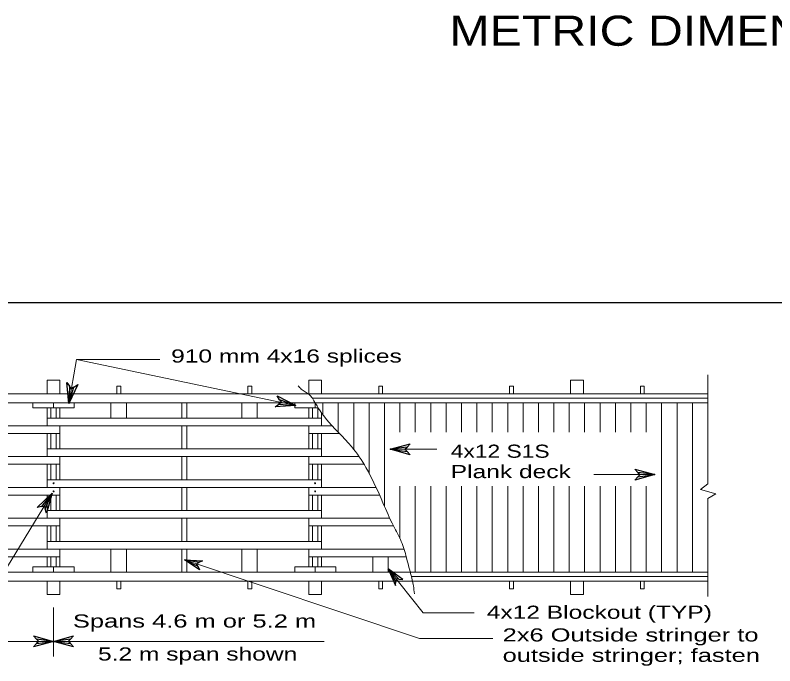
# Model space of a CAD drawing. Extents: x 13426 to 15509, y -9298 to -5111.
# Drawn here: x 15245.4 to 15321.1, y -5416 to -5351.2 of the extents above; entities that cross this region are included whole.
import ezdxf
from ezdxf.enums import TextEntityAlignment as Align

# ---------------------------------------------------------------- set-up
doc = ezdxf.new("R2010")
doc.units = 0
doc.header["$LTSCALE"] = 0.52
for name, color, linetype, lineweight in [('1', 7, 'Continuous', 13), ('11', 7, 'Continuous', 13), ('15', 7, 'Continuous', 13), ('16', 7, 'Continuous', 25), ('2', 7, 'Continuous', 25), ('20', 7, 'Continuous', 13), ('3', 7, 'Continuous', 25), ('30', 7, 'Continuous', 25), ('4', 7, 'Continuous', 13), ('5', 7, 'Continuous', 25), ('6', 7, 'Continuous', 13)]:
    doc.layers.add(name, color=color, linetype=linetype, lineweight=lineweight)
doc.layers.add('19', color=7, linetype='Continuous')

msp = doc.modelspace()

# ---------------------------------------------------------------- linework, layer by layer
at = {"layer": '1'}
for p, q in [((15314.42, -5397.839), (15314.42, -5386.994)), ((15248.583, -5387.513), (15249.861, -5387.513)), ((15248.583, -5388.864), (15248.583, -5387.513)), ((15249.861, -5388.864), (15249.861, -5387.513)), ((15275.94, -5387.513), (15274.662, -5387.513)), ((15274.662, -5388.864), (15274.662, -5387.513)), ((15275.94, -5388.864), (15275.94, -5387.513)), ((15300.741, -5388.864), (15300.741, -5387.513)), ((15302.019, -5387.513), (15300.741, -5387.513)), ((15302.019, -5388.864), (15302.019, -5387.513)), ((15255.55, -5388.119), (15255.933, -5388.119)), ((15255.55, -5388.119), (15255.55, -5388.864)), ((15255.933, -5388.119), (15255.933, -5388.864)), ((15268.59, -5388.119), (15268.973, -5388.119)), ((15268.59, -5388.119), (15268.59, -5388.864)), ((15268.973, -5388.119), (15268.973, -5388.864)), ((15281.629, -5388.119), (15282.012, -5388.119)), ((15281.629, -5388.119), (15281.629, -5388.864)), ((15282.012, -5388.119), (15282.012, -5388.864)), ((15294.669, -5388.119), (15295.052, -5388.119)), ((15294.669, -5388.119), (15294.669, -5388.864)), ((15295.052, -5388.119), (15295.052, -5388.864)), ((15308.091, -5388.119), (15307.708, -5388.119)), ((15307.708, -5388.119), (15307.708, -5388.864)), ((15308.091, -5388.119), (15308.091, -5388.864)), ((15314.42, -5388.864), (15196.297, -5388.864)), ((15314.42, -5389.311), (15275.02, -5389.311)), ((15314.42, -5389.758), (15196.297, -5389.758)), ((15248.583, -5390.273), (15248.583, -5392.06)), ((15249.861, -5390.273), (15249.861, -5391.293)), ((15274.662, -5390.273), (15274.662, -5391.293)), ((15275.94, -5390.778), (15275.94, -5392.06)), ((15249.861, -5392.06), (15249.861, -5394.361)), ((15274.662, -5392.06), (15274.662, -5394.361)), ((15248.583, -5392.827), (15248.583, -5395.128)), ((15275.94, -5392.827), (15275.94, -5395.128)), ((15249.861, -5395.128), (15249.861, -5397.43)), ((15274.662, -5395.128), (15274.662, -5397.43)), ((15248.583, -5395.896), (15248.583, -5398.196)), ((15275.94, -5395.896), (15275.94, -5398.196)), ((15249.861, -5398.196), (15249.861, -5400.497)), ((15274.662, -5398.196), (15274.662, -5400.497)), ((15248.583, -5398.963), (15248.583, -5401.264)), ((15275.94, -5398.963), (15275.94, -5401.264)), ((15314.42, -5409.06), (15314.42, -5399.293)), ((15249.861, -5401.264), (15249.861, -5403.566)), ((15274.662, -5401.264), (15274.662, -5403.566)), ((15248.583, -5402.031), (15248.583, -5404.333)), ((15275.94, -5402.031), (15275.94, -5404.333)), ((15249.861, -5404.333), (15249.861, -5406.12)), ((15274.662, -5404.333), (15274.662, -5406.12)), ((15248.583, -5405.1), (15248.583, -5406.12)), ((15275.94, -5405.1), (15275.94, -5406.12)), ((15314.42, -5406.632), (15196.297, -5406.632)), ((15314.42, -5407.516), (15196.297, -5407.516)), ((15248.583, -5407.518), (15248.583, -5408.869)), ((15249.861, -5408.869), (15249.861, -5407.518)), ((15255.55, -5408.301), (15255.55, -5407.526)), ((15255.933, -5408.301), (15255.933, -5407.526)), ((15268.59, -5408.301), (15268.59, -5407.526)), ((15268.973, -5408.301), (15268.973, -5407.526)), ((15274.662, -5408.869), (15274.662, -5407.518)), ((15275.94, -5407.518), (15275.94, -5408.869)), ((15281.629, -5408.301), (15281.629, -5407.526)), ((15282.012, -5408.301), (15282.012, -5407.526)), ((15314.42, -5407.069), (15284.876, -5407.069)), ((15295.052, -5408.301), (15295.052, -5407.526)), ((15300.741, -5408.869), (15300.741, -5407.518)), ((15302.019, -5407.518), (15302.019, -5408.869)), ((15307.708, -5408.301), (15307.708, -5407.526)), ((15308.091, -5408.301), (15308.091, -5407.526)), ((15255.933, -5408.301), (15255.55, -5408.301)), ((15268.973, -5408.301), (15268.59, -5408.301)), ((15282.012, -5408.301), (15281.629, -5408.301)), ((15308.091, -5408.301), (15307.708, -5408.301)), ((15248.583, -5408.869), (15249.861, -5408.869)), ((15275.94, -5408.869), (15274.662, -5408.869)), ((15302.019, -5408.869), (15300.741, -5408.869))]:
    msp.add_line(p, q, dxfattribs=at)
for points in [[(15314.42, -5397.839), (15313.691, -5398.393), (15315.226, -5398.819), (15314.42, -5399.293)], [(15295.052, -5408.301), (15294.669, -5408.301), (15294.669, -5407.526)]]:
    msp.add_lwpolyline(points, dxfattribs=at)
for points in [[(15275.021, -5389.312), (15274.695, -5388.946), (15273.914, -5388.406), (15273.588, -5388.07)], [(15275.021, -5389.312), (15276.322, -5391.306), (15278.926, -5394.137), (15280.358, -5396.227), (15282.051, -5399.733), (15283.092, -5402.025), (15283.873, -5403.576), (15284.394, -5405.194), (15285.038, -5407.701)]]:
    msp.add_spline(points, degree=3, dxfattribs=at)
at = {"layer": '11'}
for p, q in [((15276.068, -5389.759), (15276.068, -5390.961)), ((15277.602, -5389.759), (15277.602, -5392.713)), ((15279.136, -5389.759), (15279.136, -5394.406)), ((15280.67, -5389.759), (15280.67, -5396.857)), ((15282.204, -5389.759), (15282.204, -5400.07)), ((15283.738, -5389.759), (15283.738, -5392.705)), ((15285.272, -5389.759), (15285.272, -5392.705)), ((15286.806, -5389.759), (15286.806, -5392.705)), ((15288.34, -5389.759), (15288.34, -5392.705)), ((15289.874, -5389.759), (15289.874, -5392.705)), ((15291.408, -5389.759), (15291.408, -5392.705)), ((15292.942, -5389.759), (15292.942, -5392.705)), ((15294.476, -5389.759), (15294.476, -5392.705)), ((15296.01, -5389.759), (15296.01, -5392.705)), ((15297.544, -5389.759), (15297.544, -5392.705)), ((15299.078, -5389.759), (15299.078, -5392.705)), ((15300.612, -5389.759), (15300.612, -5392.705)), ((15302.146, -5389.759), (15302.146, -5392.705)), ((15303.68, -5389.759), (15303.68, -5392.705)), ((15305.214, -5389.759), (15305.214, -5392.705)), ((15306.748, -5389.759), (15306.748, -5392.705)), ((15308.282, -5389.759), (15308.282, -5392.705)), ((15309.817, -5389.758), (15309.817, -5406.632)), ((15311.35, -5389.759), (15311.35, -5392.705)), ((15311.351, -5389.758), (15311.351, -5406.632)), ((15312.885, -5389.758), (15312.885, -5406.632)), ((15283.738, -5398.067), (15283.738, -5403.283)), ((15285.273, -5398.067), (15285.273, -5406.632)), ((15286.807, -5398.067), (15286.807, -5406.632)), ((15288.341, -5398.067), (15288.341, -5406.632)), ((15289.874, -5398.067), (15289.874, -5406.632)), ((15291.408, -5398.067), (15291.408, -5406.632)), ((15292.943, -5398.067), (15292.943, -5406.632)), ((15294.477, -5398.067), (15294.477, -5406.632)), ((15296.011, -5398.067), (15296.011, -5406.632)), ((15297.545, -5398.067), (15297.545, -5406.632)), ((15299.079, -5398.067), (15299.079, -5406.632)), ((15300.613, -5398.067), (15300.613, -5406.632)), ((15302.147, -5398.067), (15302.147, -5406.632)), ((15303.681, -5398.067), (15303.681, -5406.632)), ((15305.215, -5398.067), (15305.215, -5406.632)), ((15306.749, -5398.067), (15306.749, -5406.632)), ((15308.283, -5398.067), (15308.283, -5406.632))]:
    msp.add_line(p, q, dxfattribs=at)
at = {"layer": '15'}
for p, q in [((15251.525, -5385.47), (15250.753, -5389.826)), ((15251.525, -5385.47), (15259.833, -5385.47)), ((15251.525, -5385.47), (15273.362, -5390.03)), ((15287.416, -5394.392), (15282.775, -5394.392)), ((15303.045, -5396.917), (15309.145, -5396.917)), ((15241.981, -5410.423), (15249.092, -5398.762)), ((15262.263, -5405.417), (15285.684, -5413.253)), ((15282.567, -5406.314), (15286.068, -5410.681)), ((15249.222, -5410.145), (15249.222, -5415.034)), ((15291.124, -5410.681), (15286.068, -5410.681)), ((15223.143, -5413.535), (15249.222, -5413.535)), ((15249.222, -5413.536), (15276.177, -5413.536)), ((15285.684, -5413.253), (15292.995, -5413.253))]:
    msp.add_line(p, q, dxfattribs=at)
at = {"layer": '16'}
for points in [[(15251.265, -5388.203), (15251.639, -5387.953), (15250.753, -5389.826), (15250.566, -5387.763), (15250.831, -5388.126), (15250.753, -5389.826), (15251.265, -5388.203), (15251.01, -5388.382), (15250.831, -5388.126)], [(15271.755, -5389.469), (15271.517, -5389.088), (15273.362, -5390.03), (15271.294, -5390.155), (15271.665, -5389.901), (15273.362, -5390.03), (15271.755, -5389.469), (15271.927, -5389.73), (15271.665, -5389.901)], [(15284.462, -5394.613), (15284.774, -5394.937), (15282.775, -5394.392), (15284.774, -5393.847), (15284.462, -5394.171), (15282.775, -5394.392), (15284.462, -5394.613), (15284.242, -5394.392), (15284.462, -5394.171)], [(15307.458, -5396.696), (15307.146, -5396.372), (15309.145, -5396.917), (15307.146, -5397.462), (15307.458, -5397.137), (15309.145, -5396.917), (15307.458, -5396.696), (15307.679, -5396.917), (15307.458, -5397.137)], [(15248.025, -5400.087), (15247.586, -5400.184), (15249.092, -5398.762), (15248.517, -5400.752), (15248.402, -5400.317), (15249.092, -5398.762), (15248.025, -5400.087), (15248.329, -5400.014), (15248.402, -5400.317)], [(15263.598, -5406.05), (15263.768, -5406.401), (15262.263, -5405.417), (15264.059, -5405.501), (15263.716, -5405.686), (15262.263, -5405.417), (15263.598, -5406.05), (15263.474, -5405.809), (15263.716, -5405.686)], [(15283.632, -5407.337), (15284.021, -5407.371), (15282.567, -5406.314), (15283.283, -5407.963), (15283.334, -5407.576), (15282.567, -5406.314), (15283.632, -5407.337), (15283.364, -5407.308), (15283.334, -5407.576)], [(15247.535, -5413.315), (15247.223, -5412.99), (15249.222, -5413.535), (15247.223, -5414.081), (15247.535, -5413.756), (15249.222, -5413.535), (15247.535, -5413.315), (15247.755, -5413.535), (15247.535, -5413.756)], [(15250.91, -5413.756), (15251.221, -5414.081), (15249.222, -5413.536), (15251.221, -5412.99), (15250.91, -5413.315), (15249.222, -5413.536), (15250.91, -5413.756), (15250.689, -5413.536), (15250.91, -5413.315)]]:
    msp.add_lwpolyline(points, dxfattribs=at)
at = {"layer": '2', "lineweight": 13}
for p, q in [((15275.94, -5391.293), (15248.583, -5391.293)), ((15276.968, -5392.06), (15222.376, -5392.06)), ((15249.861, -5392.827), (15222.504, -5392.827)), ((15246.807, -5392.827), (15249.861, -5392.827)), ((15277.716, -5392.827), (15274.662, -5392.827)), ((15275.94, -5394.361), (15248.583, -5394.361)), ((15279.679, -5395.128), (15222.376, -5395.128)), ((15249.861, -5395.896), (15222.504, -5395.896)), ((15280.178, -5395.896), (15274.662, -5395.896)), ((15275.94, -5397.43), (15248.583, -5397.43)), ((15281.329, -5398.196), (15222.376, -5398.196)), ((15249.861, -5398.963), (15222.504, -5398.963)), ((15281.691, -5398.963), (15274.662, -5398.963)), ((15275.94, -5400.497), (15248.583, -5400.497)), ((15282.747, -5401.264), (15222.376, -5401.264)), ((15249.861, -5402.031), (15222.504, -5402.031)), ((15283.096, -5402.031), (15274.662, -5402.031)), ((15275.94, -5403.566), (15248.583, -5403.566)), ((15284.148, -5404.333), (15222.376, -5404.333)), ((15249.861, -5405.1), (15222.504, -5405.1)), ((15284.369, -5405.1), (15274.662, -5405.1))]:
    msp.add_line(p, q, dxfattribs=at)
msp.add_spline([(15285.038, -5407.701), (15285.087, -5407.999), (15285.176, -5408.79)], degree=3, dxfattribs=at)
at = {"layer": '3', "lineweight": 13}
for p, q in [((15247.177, -5390.273), (15247.177, -5389.761)), ((15249.222, -5390.273), (15249.222, -5389.791)), ((15275.301, -5390.273), (15275.301, -5389.791)), ((15247.177, -5390.273), (15249.222, -5390.273)), ((15249.222, -5406.12), (15247.177, -5406.12)), ((15247.177, -5406.12), (15247.177, -5406.632)), ((15251.267, -5406.12), (15249.222, -5406.12)), ((15249.222, -5406.12), (15249.222, -5406.632)), ((15251.267, -5406.12), (15251.267, -5406.632)), ((15273.255, -5406.12), (15275.301, -5406.12)), ((15273.255, -5406.12), (15273.255, -5406.632)), ((15275.301, -5406.12), (15277.347, -5406.12)), ((15275.301, -5406.12), (15275.301, -5406.632)), ((15277.347, -5406.12), (15277.347, -5406.632))]:
    msp.add_line(p, q, dxfattribs=at)
for points in [[(15249.222, -5390.273), (15251.267, -5390.273), (15251.267, -5389.761)], [(15275.6, -5390.273), (15273.255, -5390.273), (15273.255, -5389.761)]]:
    msp.add_lwpolyline(points, dxfattribs=at)
at = {"layer": '30'}
msp.add_line((15509.151, -5379.809), (15181.119, -5379.809), dxfattribs=at)
at = {"layer": '4'}
for p, q in [((15262.006, -5391.294), (15262.006, -5389.76)), ((15262.517, -5391.294), (15262.517, -5389.76)), ((15248.967, -5390.273), (15248.967, -5391.293)), ((15249.478, -5390.273), (15249.478, -5391.293)), ((15275.045, -5390.273), (15275.045, -5391.293)), ((15275.557, -5390.273), (15275.557, -5391.293)), ((15262.006, -5392.061), (15262.006, -5394.362)), ((15262.517, -5392.061), (15262.517, -5394.362)), ((15248.967, -5392.827), (15248.967, -5394.361)), ((15249.478, -5392.827), (15249.478, -5394.361)), ((15275.045, -5392.827), (15275.045, -5394.361)), ((15275.557, -5392.827), (15275.557, -5394.361)), ((15262.006, -5395.129), (15262.006, -5397.43)), ((15262.517, -5395.129), (15262.517, -5397.43)), ((15248.967, -5395.896), (15248.967, -5397.43)), ((15249.478, -5395.896), (15249.478, -5397.43)), ((15275.045, -5395.896), (15275.045, -5397.43)), ((15275.557, -5395.896), (15275.557, -5397.43)), ((15262.006, -5398.197), (15262.006, -5400.498)), ((15262.517, -5398.197), (15262.517, -5400.498)), ((15248.967, -5398.963), (15248.967, -5400.497)), ((15249.478, -5398.963), (15249.478, -5400.497)), ((15275.045, -5398.963), (15275.045, -5400.497)), ((15275.557, -5398.963), (15275.557, -5400.497)), ((15262.006, -5401.265), (15262.006, -5403.566)), ((15262.517, -5401.265), (15262.517, -5403.566)), ((15248.967, -5402.031), (15248.967, -5403.566)), ((15249.478, -5402.031), (15249.478, -5403.566)), ((15275.045, -5402.031), (15275.045, -5403.566)), ((15275.557, -5402.031), (15275.557, -5403.566)), ((15262.006, -5406.632), (15262.006, -5404.333)), ((15262.517, -5406.632), (15262.517, -5404.333)), ((15248.967, -5405.1), (15248.967, -5406.12)), ((15249.478, -5405.1), (15249.478, -5406.12)), ((15275.045, -5405.1), (15275.045, -5406.12)), ((15275.557, -5405.1), (15275.557, -5406.12))]:
    msp.add_line(p, q, dxfattribs=at)
at = {"layer": '5', "lineweight": 13}
for p, q in [((15254.95, -5391.295), (15254.95, -5389.761)), ((15256.49, -5391.295), (15256.49, -5389.761)), ((15267.991, -5391.298), (15267.991, -5389.764)), ((15269.531, -5391.298), (15269.531, -5389.764)), ((15254.95, -5406.632), (15254.95, -5404.333)), ((15256.49, -5406.632), (15256.49, -5404.333)), ((15267.989, -5406.632), (15267.989, -5404.333)), ((15269.528, -5406.632), (15269.528, -5404.333)), ((15281.027, -5406.632), (15281.027, -5405.1)), ((15282.567, -5406.632), (15282.567, -5405.1))]:
    msp.add_line(p, q, dxfattribs=at)
at = {"layer": '6'}
for centre in [(15249.235, -5397.7855), (15275.288, -5397.7855), (15249.2291, -5398.5868), (15275.2939, -5398.5868)]:
    msp.add_circle(centre, 0.0479, dxfattribs=at)

# ---------------------------------------------------------------- texts
at = {"layer": '1', "width": 1.2}
msp.add_text('METRIC DIMENSIONS ARE SHOWN ON LEVEL 19', height=3, dxfattribs=at).set_placement((15288.661, -5354.212))
at = {"layer": '19'}
for s, width, p in [('910 mm 4x16 splices', 1.4, (15260.943, -5385.761)), ('2x6 Outside stringer to', 1.45, (15293.973, -5413.539)), ('outside stringer; fasten', 1.45, (15293.973, -5415.567))]:
    msp.add_text(s, height=1.307, dxfattribs=dict(at, width=width)).set_placement(p)
for s, width, p in [('Spans 4.6 m or 5.2 m', 1.45, (15263.2725, -5412.153)), ('5.2 m span shown', 1.4, (15263.5845, -5415.438))]:
    msp.add_text(s, height=1.307, dxfattribs=dict(at, width=width)).set_placement(p, align=Align.CENTER)
at = {"layer": '20'}
for s, width, p in [('4x12 S1S', 1.3, (15288.802, -5395.243)), ('Plank deck', 1.4, (15288.802, -5397.271)), ('4x12 Blockout (TYP)', 1.4, (15292.388, -5411.279))]:
    msp.add_text(s, height=1.307, dxfattribs=dict(at, width=width)).set_placement(p)

doc.saveas('drawing.dxf')
